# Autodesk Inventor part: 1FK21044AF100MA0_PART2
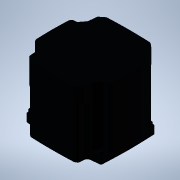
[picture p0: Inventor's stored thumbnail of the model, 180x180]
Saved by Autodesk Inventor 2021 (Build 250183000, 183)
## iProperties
Created: 2025-04
Part Number: 1FK21044AF100MA0_PART2
Material: Generic
Catalog Web Link: www.3dfindit.com
Description: -Servo synchronous motor
Document SubType Name: Modeling
Designer: psAdmin
Mass: 372.123 g
Surface Area: 313.117 cm^2
Volume: 372.123 cm^3
Density: 1 g/cm^3
Appearance: PSOLRGB-38-46-56
Category: PARTsolutions
Title: 1FK21044AF100MA0_PART2
Author: Cadenas PARTsolutions
Comments: Servo synchronous motor
Sending System: PARTsolutions
Preprocessor: ST-DEVELOPER v19.3
PSOL_IDENT_0: {$CADENAS_DATA/23d-libs/siemens_ag/_cat_/ec/e4/1fk21044af100ma0.prj},213 {VTYP=3D},{NB=1FK21044AF100
PSOL_IDENT_1: MA0_PART2},{LINA=1FK21044AF100MA0_PART2},{NN=1FK21044AF100MA0_PART2},{NOPRJ=TRUE},{DATE=19.08.2025 1
PSOL_IDENT_2: 4:01:05},{GEOMDATE=30.07.2025 02:01:01},{VERSION=},{LINEID=10},{WBVAR=},{WBNUMERIC=}  {NB=1FK21044AF
PSOL_IDENT_3: 100MA0_PART2},{LINA=1FK21044AF100MA0_PART2},{KT=DUMMY},{PREVIEW=../../../_pool_/cb/72/p_d211_xx_0043
PSOL_IDENT_4: 4j.png},{DESCSHORT=SIMOTICS S-1FK2 HD, SINAMICS S210 3AC 400V-480V, 1.27 Nm, 3000 rpm},{DESCLONG=SIM
PSOL_IDENT_5: OTICS S-1FK2 HD servo motor M0=1.27 Nm; PN = 0.4 kW at nN=3000 rpm (380-480 V); PN = 0.2 kW at nN=15
PSOL_IDENT_6: 00 rpm (200-240 V); with holding brake; degree of protection IP64; cylindrical shaft D19x40mm; absol
PSOL_IDENT_7: ute encoder 22-bit + 12-bit multiturn (encoder AM22DQC); with OCC interface; plug size M17, rotatabl
PSOL_IDENT_8: e; SIMOTICS S-1FK2 servomotorfor a wide range of uses in industrial environments. SIMOTICS S‑1FK2 se
PSOL_IDENT_9: rvomotors are compact synchronous motors with a high dynamic performance that set themselves apart a
PSOL_IDENT_10: s a result of their high power density, degree of protection and overload capability. The motors are
PSOL_IDENT_11: available in two variants: as High Dynamic variant (highest dynamic performance as a result of the
PSOL_IDENT_12: low intrinsic moment of inertia for applications demanding a high dynamic performance with low moved
PSOL_IDENT_13: masses) - and as Compact variant (precise and stable closed-loop control for medium up to large mov
PSOL_IDENT_14: ed masses as a result of a medium intrinsic moment of inertia). SIMOTICSS‑1FK2 servomotors fully exp
PSOL_IDENT_15: loit their strengths in a system with the SINAMICSS210 frequency converter and simple connection usi
PSOL_IDENT_16: ng the one cable connection (OCC). Advantages include the short control and positioning times, fast
PSOL_IDENT_17: and precise correction of disturbing quantities as well as stable control with a high dynamic perfor
PSOL_IDENT_18: mance. The servo motors can be configured to address a wide range of requirements. For example with
PSOL_IDENT_19: and without holding brake, IP64 or IP65 degree of protection, singleturn or multiturn absolute encod
PSOL_IDENT_20: ers - to name just a few. Further, the servomotors are available in different shaft heights extendin
PSOL_IDENT_21: g from 20 to 100. A shaft sealing ring is available to achieve an IP65 degree of protection and for
PSOL_IDENT_22: subsequent mounting at the motor or as spare part. SIMOTICS - the optimum motor for each and every m
PSOL_IDENT_23: otion control application.},{INTNO=195125043275},{SUPPLIERALTNO=1FK2104-4AF10-0MA0},{MANUID=1FK21044
PSOL_IDENT_24: AF100MA0},{MANUNAME=Siemens},{MANUTYPEDESC=Synchronous motor 1FK2-HD 1.27 NM},{AAU732=SIMOTICS},{AAO
PSOL_IDENT_25: 057=S-1FK2},{AAU734=SIMOTICS S-1FK2 HD servo motor M0=1.27 Nm; PN = 0.4 kW at nN=3000 rpm (380-480 V
PSOL_IDENT_26: ); PN = 0.2 kW at nN=1500 rpm (200-240 V); with holding brake; degree of protection IP64; cylindrica
PSOL_IDENT_27: l shaft D19x40mm; absolute encoder 22-bit + 12-bit multiturn (encoder AM22DQC); with OCC interface;
PSOL_IDENT_28: plug size M17, rotatable;},{AAW338=Synchronous motor 1FK2-HD 1.27 NM},{AAO742=SIMOTICS},{AAO663=4042
PSOL_IDENT_29: 948694015},{NOCUPEROU=1},{PRICEQUANTITY=1},{QUANTITYMIN=1},{QUANTITYINT=1},{CTN=85015100},{COO=DE},{
PSOL_IDENT_30: AAO676=1FK2104-4AF10-0MA0},{AAO677=Siemens AG},{ORDERUNIT=C62},{CONTENTUNIT=C62}
NB: 1FK21044AF100MA0_PART2
NT: Servo synchronous motor
NBSYN: $MANUID._PART2
LINA: 1FK21044AF100MA0_PART2
CATALOG: SIEMENS
PREVIEW: ../../../_pool_/cb/72/p_d211_xx_00434j.png
DESCSHORT: SIMOTICS S-1FK2 HD, SINAMICS S210 3AC 400V-480V, 1.27 Nm, 3000 rpm
DESCLONG: SIMOTICS S-1FK2 HD servo motor M0=1.27 Nm; PN = 0.4 kW at nN=3000 rpm (380-480 V); PN = 0.2 kW at nN=1500 rpm (200-240 V); with holding brake; degree of protect
INTNO: 195125043275
SUPPLIERALTNO: 1FK2104-4AF10-0MA0
MANUID: 1FK21044AF100MA0
MANUNAME: Siemens
MANUTYPEDESC: Synchronous motor 1FK2-HD 1.27 NM
AAU732: SIMOTICS
AAO057: S-1FK2
AAU734: SIMOTICS S-1FK2 HD servo motor M0=1.27 Nm; PN = 0.4 kW at nN=3000 rpm (380-480 V); PN = 0.2 kW at nN=1500 rpm (200-240 V); with holding brake; degree of protect
AAW338: Synchronous motor 1FK2-HD 1.27 NM
AAO742: SIMOTICS
AAO663: 4042948694015.0
NOCUPEROU: 1
PRICEQUANTITY: 1
QUANTITYMIN: 1
QUANTITYINT: 1
CTN: 85015100
COO: DE
ARTICLENO: 1FK21044AF100MA0_PART2
BOMINFO: 1FK21044AF100MA0_PART2
CREATOR: CADENAS GmbH
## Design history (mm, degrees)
feature "2025_04_17_15_33_01_0548"
body "Solid1"
